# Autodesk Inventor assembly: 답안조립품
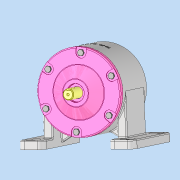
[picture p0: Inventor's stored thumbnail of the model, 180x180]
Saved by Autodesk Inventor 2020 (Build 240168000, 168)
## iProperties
Created: 2025-12
Part Number: 답안조립품
Document SubType Name: Weldment
Designer: PC2-06
Weld Material: Welded Aluminum-6061
Author: PC2-06
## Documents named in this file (16)
- C:\Users\PC2-06\Desktop\751203V1020\답안조립품.iam
- C:\Users\PC2-06\Desktop\751203V1020\본체.ipt
- C:\Users\PC2-06\Desktop\751203V1020\깊은 홈 볼 베어링 6004.ipt
- C:\Users\PC2-06\Desktop\751203V1020\기어 축.ipt
- C:\Users\PC2-06\Desktop\751203V1020\C형 멈춤링 구멍용 42.ipt
- C:\Users\PC2-06\Desktop\751203V1020\칼라 1.ipt
- C:\Users\PC2-06\Desktop\751203V1020\평행 키 6x6x16.ipt
- C:\Users\PC2-06\Desktop\751203V1020\구동 기어.ipt
- C:\Users\PC2-06\Desktop\751203V1020\엔드 캡.ipt
- C:\Users\PC2-06\Desktop\751203V1020\6각 구멍붙이 볼트 M4x10.ipt
- C:\Users\PC2-06\Desktop\751203V1020\출력 축.ipt
- C:\Users\PC2-06\Desktop\751203V1020\종동 기어.ipt
- C:\Users\PC2-06\Desktop\751203V1020\칼라 2.ipt
- C:\Users\PC2-06\Desktop\751203V1020\커버.ipt
- C:\Users\PC2-06\Desktop\751203V1020\깊은 홈 볼 베어링 6005.ipt
- C:\Users\PC2-06\Desktop\751203V1020\6각 머리 볼트 M8x20.ipt
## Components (9 placed, 4 different names)
1. C형 멈춤링 구멍용 42:1
2. 구동 기어:1
3. 6각 구멍붙이 볼트 M4x10:1
4. 6각 머리 볼트 M8x20:6
5. 6각 머리 볼트 M8x20:8
6. 6각 머리 볼트 M8x20:9
7. 6각 머리 볼트 M8x20:10
8. 6각 머리 볼트 M8x20:11
9. 6각 머리 볼트 M8x20:12
